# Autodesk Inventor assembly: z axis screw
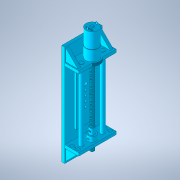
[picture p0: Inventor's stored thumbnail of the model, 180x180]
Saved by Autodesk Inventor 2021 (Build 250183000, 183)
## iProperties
Created: 2026-10
Part Number: z axis screw
Document SubType Name: Assembly
Designer: hp
Author: hp
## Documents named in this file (14)
- C:\Users\hp\Documents\Inventor\DOM1_CartesianRobot\z axis screw.iam
- C:\Users\hp\Documents\Inventor\DOM1_CartesianRobot\small_Z_Back.ipt
- C:\Users\hp\Documents\Inventor\DOM1_CartesianRobot\small_Z_Buttom.ipt
- C:\Users\hp\Documents\Inventor\DOM1_CartesianRobot\small_Z_Top.ipt
- C:\Users\hp\Documents\Inventor\DOM1_CartesianRobot\rip_1.ipt
- C:\Users\hp\Documents\Inventor\DOM1_CartesianRobot\rip_2.ipt
- C:\Users\hp\Documents\Inventor\DOM1_CartesianRobot\rip_3.ipt
- C:\Users\hp\Documents\Inventor\DOM1_CartesianRobot\rip_4.ipt
- C:\Users\hp\Documents\Inventor\DOM1_CartesianRobot\8mm_Bar_150mm.ipt
- C:\Users\hp\Documents\Inventor\DOM1_CartesianRobot\8mm_Bar_150mm_1.ipt
- C:\Users\hp\Documents\Inventor\DOM1_CartesianRobot\688_bearing_1.ipt
- C:\Users\hp\Documents\Inventor\DOM1_CartesianRobot\Lead Screw T8X8X500_150.ipt
- C:\Users\hp\Documents\Inventor\DOM1_CartesianRobot\25GA370 red26.ipt
- C:\Users\hp\Documents\Inventor\DOM1_CartesianRobot\Coupling 4mm x 8mm.ipt
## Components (13 placed, 13 different names)
1. small_Z_Back:1 — Mate:1, Mate:2, Flush:1, Mate:3, Mate:4, Flush:2, Mate:5, Mate:6, Flush:3, Mate:7, Mate:8, Flush:4, Mate:9, Mate:10, Flush:5, Mate:11, Flush:6, Mate:12
2. small_Z_Buttom:1 — Mate:1, Mate:2, Flush:1
3. small_Z_Top:1 — Mate:11, Flush:6, Mate:12, Mate:13, Mate:14, Mate:15
4. rip_1:1 — Mate:5, Mate:6, Flush:3
5. rip_2:1 — Mate:3, Mate:4, Flush:2
6. rip_3:1 — Mate:9, Mate:10, Flush:5
7. rip_4:1 — Mate:7, Mate:8, Flush:4
8. 8mm_Bar_150mm:1
9. 8mm_Bar_150mm_1:1
10. 688_bearing_1:1 — Mate:19
11. Lead Screw T8X8X500_150:1 — Mate:16, Mate:17, Mate:18
12. 25GA370 red26:1 — Mate:13, Mate:14, Mate:15, Mate:16, Mate:17
13. Coupling 4mm x 8mm:1 — Mate:18, Mate:19
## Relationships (25: Mate 19, Flush 6)
- Mate:1: small_Z_Back:1 ↔ small_Z_Buttom:1
- Mate:2: small_Z_Back:1 ↔ small_Z_Buttom:1
- Flush:1: small_Z_Back:1 ↔ small_Z_Buttom:1
- Mate:3: small_Z_Back:1 ↔ rip_2:1
- Mate:4: small_Z_Back:1 ↔ rip_2:1
- Flush:2: small_Z_Back:1 ↔ rip_2:1
- Mate:5: small_Z_Back:1 ↔ rip_1:1
- Mate:6: small_Z_Back:1 ↔ rip_1:1
- Flush:3: small_Z_Back:1 ↔ rip_1:1
- Mate:7: small_Z_Back:1 ↔ rip_4:1
- Mate:8: small_Z_Back:1 ↔ rip_4:1
- Flush:4: small_Z_Back:1 ↔ rip_4:1
- Mate:9: small_Z_Back:1 ↔ rip_3:1
- Mate:10: small_Z_Back:1 ↔ rip_3:1
- Flush:5: small_Z_Back:1 ↔ rip_3:1
- Mate:11: small_Z_Back:1 ↔ small_Z_Top:1
- Flush:6: small_Z_Back:1 ↔ small_Z_Top:1
- Mate:12: small_Z_Back:1 ↔ small_Z_Top:1
- Mate:13: small_Z_Top:1 ↔ 25GA370 red26:1
- Mate:14: small_Z_Top:1 ↔ 25GA370 red26:1
- Mate:15: small_Z_Top:1 ↔ 25GA370 red26:1
- Mate:16: Lead Screw T8X8X500_150:1 ↔ 25GA370 red26:1
- Mate:17: Lead Screw T8X8X500_150:1 ↔ 25GA370 red26:1
- Mate:18: Lead Screw T8X8X500_150:1 ↔ Coupling 4mm x 8mm:1
- Mate:19: 688_bearing_1:1 ↔ Coupling 4mm x 8mm:1
